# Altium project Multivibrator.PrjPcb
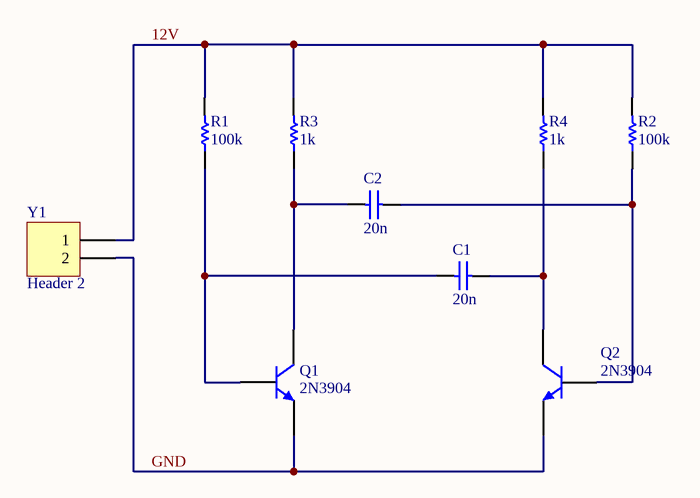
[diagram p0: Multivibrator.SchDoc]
1 sheet, 9 parts. Net scope: global (net labels, ports and power ports of the same name join across sheets).
Board file: Multivibrator.PcbDoc

## Sheet Multivibrator.SchDoc
size A4

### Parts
C1  20n  [RAD-0.3]
C2  20n  [RAD-0.3]
Q1  2N3904  [BCY-W3/E4]
Q2  2N3904  [BCY-W3/E4]
R1  100k  [AXIAL-0.3]
R2  100k  [AXIAL-0.3]
R3  1k  [AXIAL-0.3]
R4  1k  [AXIAL-0.3]
Y1  Header 2  [HDR1X2]

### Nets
12V: R1.2 R2.2 R3.2 R4.2 Y1.1
GND: Q1.1(E) Q2.1(E) Y1.2
NetC1_1: C1.1 Q1.2(B) R1.1
NetC1_2: C1.2 Q2.3(C) R4.1
NetC2_1: C2.1 Q1.3(C) R3.1
NetC2_2: C2.2 Q2.2(B) R2.1

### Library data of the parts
C1 C2 = Cap: Capacitor; Value: 100pF
Q1 Q2 = 2N3904: NPN General Purpose Amplifier
R1 R2 = Res1: Resistor; Value: 1K
R3 R4 = Res1: Resistor
Y1 = Header 2: Header, 2-Pin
